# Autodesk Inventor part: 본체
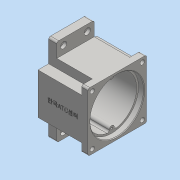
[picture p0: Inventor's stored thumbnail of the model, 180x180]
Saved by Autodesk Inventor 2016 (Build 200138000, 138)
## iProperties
Created: 2020-08
Part Number: 본체
Material: 일반
Document SubType Name: Modeling
Designer: User
Density: 1 g/cm^3
Appearance: 기본값
Author: User
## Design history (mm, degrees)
sketch "스케치1"
  geometry: L1 (30, 70)-(-30, 70); L2 (-30, 70)-(-30, -70); L3 (-30, -70)-(30, -70); L4 (30, -70)-(30, 70); L5 (30, 70)-(-30, -70); L6 (-30, 70)-(30, -70); L7 (47, 33)-(-47, 33); L8 (-47, 33)-(-47, -33); L9 (-47, -33)-(47, -33); L10 (47, -33)-(47, 33); L11 (47, 33)-(-47, -33); L12 (-47, 33)-(47, -33); 1 further point
  constraints: 24 end point, 4 midpoint, 4 parallel, 2 horizontal, 2 perpendicular
  dimensions: "d2" = 140 distance between parallel lines of L3 L1; "d3" = 60 distance between parallel lines of L2 L4; "d4" = 66 distance of L9.end L7.start; "d5" = 94 distance between parallel lines of L8 L10
extrude "돌출1" new body sketch "스케치1" distance "d6" = 13; taper "d7" = 0 deg
sketch "스케치3"
  geometry: L1 (-47, 47)-(47, 47); L2 (47, 47)-(47, -47); L3 (47, -47)-(-47, -47); L4 (-47, -47)-(-47, 47); L5 (-47, 47)-(47, -47); L6 (47, 47)-(-47, -47); 1 further point
  constraints: 12 end point, 2 midpoint, 2 parallel, 1 horizontal, 1 perpendicular
  dimensions: "d8" = 94 distance of L2.end L3.end; "d9" = 94 distance of L1.end L2.end
extrude "돌출2" join sketch "스케치3" distance "d10" = 67; taper "d11" = 0 deg
sketch "스케치4"
  geometry: L1 (33, -30)-(33, -47) reference; L2 (33, -47)-(47, -47) reference; L3 (47, -47)-(47, -30) reference; L4 (47, -30)-(33, -30) reference; L5 (-33, -47)-(-33, -30) reference; L6 (-33, -30)-(-47, -30) reference; L7 (-47, -30)-(-47, -47) reference; L8 (-47, -47)-(-33, -47) reference; L9 (-47, 30)-(-33, 30) reference; L10 (-33, 30)-(-33, 47) reference; L11 (-33, 47)-(-47, 47) reference; L12 (-47, 47)-(-47, 30) reference; L13 (33, 30)-(47, 30) reference; L14 (47, 30)-(47, 47) reference; L15 (47, 47)-(33, 47) reference; L16 (33, 47)-(33, 30) reference; 1 further point
extrude "돌출3" cut sketch "스케치4" distance "d12" = 57; taper "d13" = 0 deg
sketch "스케치5"
  geometry: C1 r 27.5 at (0, -11); 1 further point
  constraints: 1 centre point, 1 vertical alignment
  dimensions: "d14" = 55 diameter of C1; "d15" = 11 distance of point (0, 0) C1.centre
extrude "돌출4" join sketch "스케치5" distance "d16" = 7; taper "d17" = 0 deg
sketch "스케치6"
  geometry: C1 r 16 at (0, 0); C2 r 27.5 at (0, 0) reference; 1 further point
  constraints: 1 centre point, 1 concentric
  dimensions: "d18" = 16 radius of C1
extrude "돌출5" cut sketch "스케치6" distance "d19" = 8.3; taper "d20" = 0 deg
sketch "스케치7"
  geometry: C1 r 43 at (0, 0); 1 further point
  constraints: 1 centre point, 1 coincident
  dimensions: "d21" = 43 radius of C1
extrude "돌출6" cut sketch "스케치7" distance "d22" = 9; taper "d23" = 0 deg
sketch "스케치8"
  geometry: C1 r 40 at (0, 0); 1 further point
  constraints: 1 centre point, 1 coincident
  dimensions: "d24" = 80 diameter of C1
extrude "돌출7" cut sketch "스케치8" distance "d25" = 62; taper "d26" = 0 deg
sketch "스케치9"
  geometry: C1 r 21 at (0, -11); C2 r 15 at (0, 20); 1 further point
  constraints: 2 centre point, 2 vertical alignment
  dimensions: "d27" = 42 diameter of C1; "d28" = 30 diameter of C2; "d29" = 11 distance of point (0, 0) C1.centre; "d30" = 20 distance of C2.centre point (0, 0)
extrude "돌출8" join sketch "스케치9" distance "d31" = 7; taper "d32" = 0 deg
sketch "스케치10"
  geometry: C1 r 17.5 at (0, -11); A1 r 21 centre (0, -11) between (-8.978, 7.984) and (8.978, 7.984) reference; 1 further point
  constraints: 1 centre point, 1 concentric
  dimensions: "d33" = 35 diameter of C1
extrude "돌출9" cut sketch "스케치10" distance "d34" = 10; taper "d35" = 0 deg
sketch "스케치11"
  geometry: C1 r 12.5 at (0, 0); C2 r 17.5 at (0, 0) reference; 1 further point
  constraints: 1 centre point, 1 concentric
  dimensions: "d36" = 12.5 radius of C1
extrude "돌출10" cut sketch "스케치11" distance "d37" = 15; taper "d38" = 0 deg
sketch "스케치12"
  geometry: C1 r 11 at (0, 20); A1 r 15 centre (0, 20) between (8.978, 7.984) and (-8.978, 7.984) reference; 1 further point
  constraints: 1 centre point, 1 concentric
  dimensions: "d39" = 22 diameter of C1
extrude "돌출11" cut sketch "스케치12" distance "d40" = 7; taper "d41" = 0 deg
sketch "스케치13"
  geometry: C1 r 9.5 at (0, 0); C2 r 11 at (0, 0) reference; 1 further point
  constraints: 1 centre point, 1 concentric
  dimensions: "d42" = 19 diameter of C1
extrude "돌출12" cut sketch "스케치13" distance "d43" = 3; taper "d44" = 0 deg
sketch "스케치14"
  geometry: C1 r 40 at (0, 0) reference; A1 r 4 centre (-36, 0) between (-36.19, -3.995) and (-36.19, 3.995); A2 r 3 centre (-36.333, -6.992) between (-36.19, -3.995) and (-39.279, -7.559); A3 r 3 centre (-36.333, 6.992) between (-39.279, 7.559) and (-36.19, 3.995); A4 r 40 centre (0, 0) between (-39.279, -7.559) and (-39.279, 7.559) reference; 1 further point
  constraints: 8 point on circle, 5 tangent, 3 centre point, 2 horizontal alignment
  dimensions: "d45" = 8 diameter of A1; "d46" = 36 distance of A1.centre point (0, 0); "d47" = 6 diameter of A2; "d48" = 6 diameter of A3
extrude "돌출13" join sketch "스케치14" stored distance "d49" = 3; taper "d50" = 0 deg
sketch "스케치16"
  geometry: C1 r 4 at (-36, 0); A1 r 4 centre (-36, 0) between (-36.19, -3.995) and (-36.19, 3.995) reference; 1 further point
  constraints: 1 centre point, 1 coincident
  dimensions: "d51" = 4 radius of C1
hole "구멍1" sketch "스케치16" at (-36, 0) diameter "d52" = 3.242; stored, may be unused: countersink angle "d56" = 90 deg, drill point angle "d58" = 118 deg; dims "d53" = 7, "d54" = 4, "d55" = 2, "d57" = 9
sketch "스케치17"
  geometry: L1 (47, -47)-(33, -47) reference; C1 r 3.5 at (40, -40); 1 further point
  constraints: 1 centre point
  dimensions: "d60" = 40 horizontal distance of point (0, 0) C1.centre; "d61" = 40 horizontal distance of point (0, 0) C1.centre; "d62" = 7 diameter of C1
extrude "돌출14" cut sketch "스케치17" distance "d63" = 10; taper "d64" = 0 deg
sketch "스케치18"
  geometry: 2 further points
  dimensions: "d71" = 60 horizontal distance of point (0, 0) point (-60, 19); "d72" = 19 vertical distance of point (0, 0) point (-60, 19)
hole "구멍2" sketch "스케치18" at (-60, 19) diameter "d73" = 4.5; stored, may be unused: countersink angle "d77" = 90 deg, drill point angle "d79" = 118 deg; dims "d74" = 7, "d75" = 10, "d76" = 5, "d78" = 15
sketch "스케치19"
  geometry: L1 (0, 66)-(0, 0) reference; 3 further points
  constraints: 1 horizontal alignment, 1 midpoint, 1 other
  dimensions: "d86" = 40 distance of point (40, 33) point (0, 33)
feature "엠보싱1" sketch "스케치19" dims "d2" = 140, "d3" = 60, "d87" = 0.5, "d88" = 0
chamfer "모따기1" distance "d89" = 1; stored, may be unused: second distance "d90" = 2, angle "d91" = 45 deg
chamfer "모따기2" distance "d92" = 0.8; stored, may be unused: second distance "d93" = 2, angle "d94" = 30 deg
fillet "모깎기1" dims "d95" = 3
fillet "모깎기2" dims "d96" = 3
node "솔리드1"
mirror "대칭1"
pattern_linear "직사각형 패턴1" dims "d67" = 80
pattern_linear "직사각형 패턴2" dims "d82" = 38
node "투영된 루프1"
node "투영된 루프2"
node "투영된 루프3"
node "투영된 루프4"
